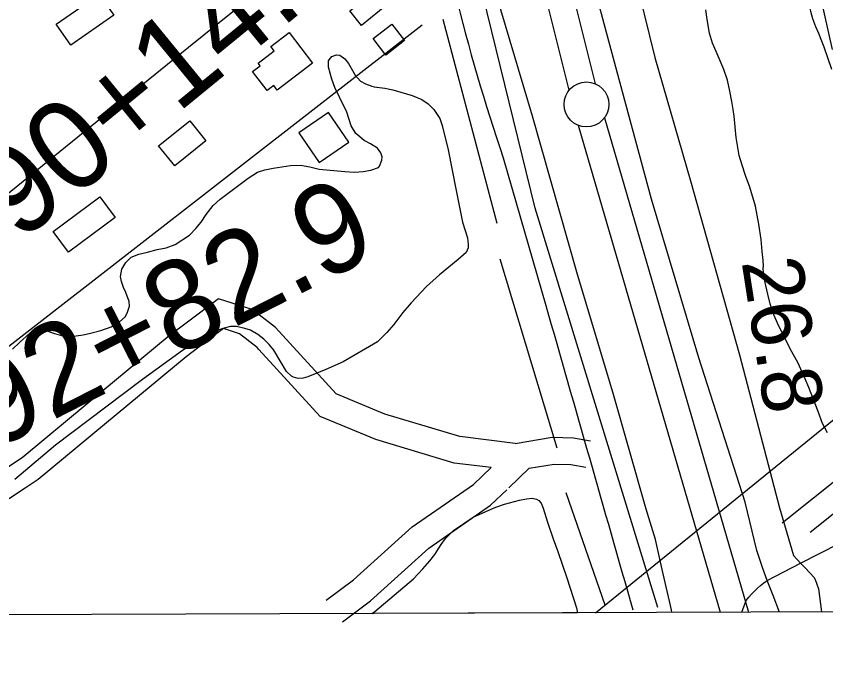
# Model space of a CAD drawing. Extents: x 3392644 to 3430565, y 576657 to 602123.
# Drawn here: x 3411444 to 3412346, y 582044 to 582765 of the extents above; entities that cross this region are included whole.
import ezdxf

# ---------------------------------------------------------------- set-up
doc = ezdxf.new("R2010")
doc.units = 0
for name, color, linetype in [('V-BLDG-OTLN', 7, 'Continuous'), ('V-FLOD-BASE', 7, 'Continuous'), ('V-GRID-FRAM', 7, 'Continuous'), ('V-LEVE-TOET', 7, 'Continuous'), ('V-RIVR-EDGE', 7, 'Continuous'), ('V-RIVR-RANG', 7, 'Continuous'), ('V-ROAD-CNTR', 7, 'Continuous'), ('V-SITE-VEGE', 7, 'Continuous'), ('V-SURV-IDEN', 7, 'Continuous'), ('V-SURV-LINE', 7, 'Continuous'), ('V-TOPO-MAJR', 7, 'Continuous'), ('V-TOPO-SHOR', 7, 'Continuous'), ('V-UTIL-LINE', 7, 'Continuous')]:
    doc.layers.add(name, color=color, linetype=linetype)

msp = doc.modelspace()

# ---------------------------------------------------------------- linework, layer by layer
at = {"layer": 'V-BLDG-OTLN'}
for points in [[(3411832.63, 582811.53), (3411859.31, 582778.84), (3411829.24, 582754.3), (3411816.1, 582770.4), (3411824.16, 582776.98), (3411810.45, 582793.78), (3411814.35, 582796.97), (3411795.96, 582819.5), (3411810.22, 582831.14), (3411828.78, 582808.39)], [(3411488.82, 582755.72), (3411536.7, 582788.93), (3411552.95, 582765.51), (3411505.06, 582732.31)], [(3411842.08, 582739.53), (3411862.93, 582755.51), (3411876.9, 582737.29), (3411856.04, 582721.3)], [(3411748.52, 582746.25), (3411774.49, 582712.2), (3411735.17, 582682.21), (3411731.29, 582687.29), (3411723.9, 582681.65), (3411707.78, 582702.77), (3411716.22, 582709.21), (3411713.94, 582712.2), (3411731.75, 582725.79), (3411728.06, 582730.64)], [(3411814.87, 582624.05), (3411792.4, 582657.14), (3411759.31, 582634.66), (3411781.78, 582601.57)], [(3411602.97, 582620), (3411637.74, 582648), (3411655.72, 582625.68), (3411620.93, 582597.69)], [(3411485.41, 582524.63), (3411537.5, 582563.22), (3411554.58, 582540.16), (3411502.49, 582501.58)]]:
    msp.add_lwpolyline(points, close=True, dxfattribs=at)
at = {"layer": 'V-FLOD-BASE'}
msp.add_lwpolyline([(3412294.62, 582100.75), (3412287.6, 582119.38), (3412281.06, 582136.05), (3412275.85, 582150.62), (3412269.35, 582169.34), (3412256.7, 582223.32), (3412204.93, 582384.16), (3412152.12, 582560.85), (3412109.91, 582717.36), (3412076.65, 582840.63), (3412048.08, 582957.6), (3412030.67, 583048.18), (3412005.56, 583165.77), (3411982.6, 583287.44), (3411961.04, 583410.47), (3411927.14, 583602.61), (3411896.14, 583801.58), (3411869.45, 583976.36), (3411833.6, 584207.11), (3411801.9, 584439.15), (3411784.08, 584609.62), (3411753.14, 584878.14), (3411722.93, 585082.61), (3411689.16, 585314)], dxfattribs=at)
at = {"layer": 'V-GRID-FRAM'}
msp.add_lwpolyline([(3396720.28, 600227.69), (3428325.66, 600342.61), (3428399.71, 582159.31), (3396778.46, 582044.33), (3396720.28, 600227.69)], dxfattribs=at)
at = {"layer": 'V-LEVE-TOET'}
for points in [[(3412175, 582100.31), (3412174.32, 582103.31), (3412164.23, 582148.28), (3412156.65, 582181.5), (3412146.34, 582215.45), (3412109.09, 582345.69), (3412069.79, 582476.66), (3412019.73, 582653.3), (3411984.31, 582771.79), (3411971.61, 582823.7), (3411961.49, 582867.29), (3411950.16, 582918.49), (3411938.26, 582975.89), (3411926.49, 583039.49), (3411908, 583144.55), (3411879.35, 583290.45), (3411840.3, 583499.91), (3411822.94, 583626.29), (3411814.63, 583690.51), (3411806.24, 583751.28), (3411782.23, 583888.82), (3411743.44, 584110.68), (3411705.8, 584355.24)], [(3411869.27, 584216.03), (3411899.49, 584046), (3411940.43, 583794.49), (3411962.95, 583651.47), (3411998.43, 583468.93), (3412031.9, 583256.14), (3412043.28, 583207.01), (3412070.87, 583076.29), (3412107.48, 582915.07), (3412155.75, 582718.5), (3412195.61, 582581.32), (3412250.13, 582387.37), (3412294.81, 582217.04), (3412310.23, 582163.7), (3412318.26, 582155.33), (3412323.04, 582150.35), (3412329.11, 582144.03), (3412333.15, 582139.81), (3412334.47, 582137.03), (3412338.39, 582126.62), (3412341.44, 582100.92)]]:
    msp.add_lwpolyline(points, dxfattribs=at)
at = {"layer": 'V-RIVR-EDGE'}
msp.add_spline([(3412059.19, 585196.29), (3412062.07, 585176.55), (3412061.68, 585167.77), (3412066.02, 585148.02), (3412070.01, 585133.76), (3412072.16, 585119.13), (3412074.7, 585110.35), (3412079.78, 585095.72), (3412081.23, 585089.5), (3412079.74, 585078.54), (3412079.36, 585072.32), (3412081.17, 585067.57), (3412084.46, 585067.19), (3412095.07, 585068.63), (3412098.72, 585067.52), (3412101.26, 585058.38), (3412103.39, 585032.42), (3412101.55, 585030.23), (3412098.62, 585028.41), (3412097.52, 585027.31), (3412097.52, 585024.39), (3412102.98, 585018.16), (3412107.71, 585007.18), (3412106.91, 584977.94), (3412102.84, 584958.58), (3412103.52, 584940.3), (3412103.51, 584934.09), (3412107.14, 584926.4), (3412112.99, 584923.83), (3412115.53, 584916.51), (3412114.78, 584908.47), (3412113.67, 584905.55), (3412117.32, 584901.15), (3412119.86, 584893.83), (3412124.19, 584870.79), (3412130.67, 584830.93), (3412135.72, 584804.6), (3412137.88, 584792.53), (3412134.94, 584783.4), (3412138.14, 584748.3), (3412137.02, 584737.7), (3412137.35, 584723.45), (3412141.69, 584704.79), (3412149.65, 584674.07), (3412155.42, 584639.32), (3412160.84, 584615.18), (3412165.17, 584590.32), (3412166.24, 584579.71), (3412169.13, 584565.08), (3412169.11, 584558.5), (3412167.64, 584554.85), (3412164.34, 584551.94), (3412166.85, 584533.29), (3412168.28, 584519.03), (3412171.16, 584502.2), (3412177.29, 584467.83), (3412184.18, 584443.68), (3412191.41, 584410.04), (3412199.71, 584367.61), (3412203.63, 584329.22), (3412206.83, 584289), (3412206.41, 584269.26), (3412208.92, 584247.69), (3412213.59, 584216.97), (3412216.5, 584210.38), (3412220.87, 584204.53), (3412226.72, 584202.32), (3412230.37, 584203.77), (3412233.29, 584201.57), (3412234.37, 584193.53), (3412234, 584192.06), (3412230.34, 584190.61), (3412233.23, 584174.15), (3412237.92, 584149.65), (3412243.71, 584125.51), (3412250.95, 584099.54), (3412250.94, 584093.69), (3412249.09, 584083.46), (3412250.16, 584076.15), (3412275.2, 584001.51), (3412285.34, 583961.28), (3412288.92, 583930.56), (3412290.33, 583910.09), (3412289.21, 583900.22), (3412292.08, 583879.38), (3412299.34, 583856.33), (3412308.04, 583829.26), (3412312.72, 583799.27), (3412319.18, 583750.64), (3412320.96, 583731.26), (3412329.26, 583686.64), (3412338.66, 583647.14), (3412344.41, 583604.35), (3412350.16, 583567.42), (3412358.82, 583520.61), (3412365.28, 583471.61), (3412371.75, 583429.19), (3412374.99, 583407.98), (3412379.36, 583398.83), (3412379.34, 583391.15), (3412378.96, 583387.86), (3412376.75, 583379.83), (3412374.91, 583375.45), (3412373.43, 583366.68), (3412373.76, 583353.88), (3412378.83, 583331.94), (3412382.46, 583325.35), (3412385.73, 583315.1), (3412394.11, 583305.21), (3412394.46, 583299.73), (3412394.44, 583288.03), (3412393.68, 583278.53), (3412393.65, 583267.93), (3412397.62, 583244.89), (3412403.03, 583217.82), (3412407.68, 583175.04), (3412422.12, 583100.44), (3412429.01, 583076.66), (3412431.89, 583060.57), (3412431.87, 583051.43), (3412434.39, 583034.97), (3412441.63, 583007.54), (3412451.39, 582962.92), (3412455.36, 582943.9), (3412459.01, 582941.33), (3412460.45, 582932.19), (3412468.39, 582890.5), (3412469.11, 582885.38), (3412468.38, 582884.65), (3412463.99, 582883.93), (3412461.79, 582881.01), (3412462.14, 582876.62), (3412467.57, 582853.21), (3412470.46, 582841.14), (3412473.74, 582838.21), (3412477.03, 582835.28), (3412479.92, 582822.48), (3412500.51, 582724.46), (3412513.18, 582673.98), (3412526.2, 582618.02), (3412557.05, 582528.02), (3412580.26, 582453.02), (3412593.31, 582406.57), (3412604.92, 582372.54), (3412613.62, 582344.01), (3412619.42, 582324.25), (3412629.98, 582308.14), (3412635.42, 582288.76), (3412638.32, 582277.42), (3412649.24, 582259.84), (3412659.04, 582231.67), (3412668.49, 582210.08), (3412681.6, 582191.41), (3412693.62, 582172), (3412707.76, 582126.27), (3412708.45, 582107.63), (3412708.05, 582102.25)], degree=3, dxfattribs=at)
at = {"layer": 'V-ROAD-CNTR'}
for points in [[(3411902.46, 582930.52), (3411896.46, 582928.28), (3411890.54, 582925.84), (3411884.71, 582923.2), (3411878.97, 582920.37), (3411873.33, 582917.34), (3411867.8, 582914.13), (3411862.37, 582910.72), (3411857.07, 582907.14), (3411851.89, 582903.38), (3411846.85, 582899.45), (3411841.94, 582895.34), (3411773.23, 582840.31), (3411704.66, 582785.1), (3411636.22, 582729.73), (3411567.92, 582674.19), (3411357.52, 582503.96), (3411036.69, 582245.97), (3410847.91, 582095.48)], [(3411987.05, 582606.77), (3412034.45, 582442.29)], [(3411726.4, 582422.94), (3411707.18, 582437.86), (3411669.78, 582449.85), (3411635.12, 582423.74)], [(3411635.12, 582423.74), (3411614.93, 582408.54), (3411523.56, 582332.87), (3411450.84, 582272.52), (3411430.26, 582258.96)], [(3412000.41, 582288.76), (3411938.65, 582296.25), (3411855.11, 582321.32), (3411800.81, 582343.97), (3411777.05, 582369.82), (3411733.22, 582417.64), (3411726.4, 582422.94)], [(3411714.74, 582393.41), (3411712.82, 582395.5), (3411692.97, 582410.91), (3411675.41, 582416.54), (3411663.57, 582407.62)], [(3411663.57, 582407.62), (3411633.53, 582384.99), (3411542.7, 582309.78), (3411468.72, 582248.38), (3411454.46, 582238.98)], [(3411973.43, 582261.81), (3411932.49, 582266.78), (3411844.99, 582293.03), (3411783.19, 582318.82), (3411754.95, 582349.53), (3411714.74, 582393.41)], [(3412000.41, 582288.76), (3412041.61, 582295.66), (3412065.36, 582295.08), (3412084.39, 582291.65)], [(3411993.35, 582239.36), (3412015.97, 582260.95), (3412043.74, 582265.6), (3412062.32, 582265.15), (3412079.06, 582262.12)], [(3411454.46, 582238.98), (3411419.06, 582215.65), (3411397.09, 582214.5), (3411366.88, 582237.13), (3411340.59, 582262.39)], [(3411789.88, 582114.1), (3411820.17, 582136.73), (3411885.33, 582195.59), (3411953.82, 582243.1), (3411973.43, 582261.81)], [(3411807.84, 582090.07), (3411839.24, 582113.53), (3411904.01, 582172.04), (3411972.84, 582219.78), (3411991.02, 582237.13)], [(3412252.9, 582100.59), (3412257.79, 582113.7), (3412260.66, 582117.36), (3412263.7, 582120.88), (3412266.89, 582124.24), (3412270.23, 582127.45), (3412273.71, 582130.5), (3412277.33, 582133.36), (3412281.06, 582136.05), (3412318.26, 582155.33), (3412425.48, 582210.06)]]:
    msp.add_lwpolyline(points, dxfattribs=at)
for centre, radius, start, end in [((3414058.65, 583313.78), 2188.92, 188.7684, 198.84414), ((3816636.06, 697993.69), 420778.55, 195.9389807, 195.9869919)]:
    msp.add_arc(centre, radius, start, end, dxfattribs=at)
at = {"layer": 'V-SITE-VEGE'}
for p, q in [((3412013.03, 582226.78), (3412019.33, 582227.54)), ((3412019.33, 582227.54), (3412024.13, 582226.75)), ((3411978.84, 582217.76), (3411988.24, 582221.1)), ((3411988.24, 582221.1), (3412005.14, 582225.47)), ((3412005.14, 582225.47), (3412013.03, 582226.78)), ((3412024.13, 582226.75), (3412026.65, 582225.03)), ((3412026.65, 582225.03), (3412029.24, 582222.03)), ((3412029.24, 582222.03), (3412031.58, 582216.47)), ((3411953.45, 582206.69), (3411967.53, 582212.69)), ((3411967.53, 582212.69), (3411978.84, 582217.76)), ((3412031.58, 582216.47), (3412036.17, 582200.95)), ((3411931.72, 582191.71), (3411953.45, 582206.69)), ((3412036.17, 582200.95), (3412042.67, 582182.54)), ((3411922.69, 582182.76), (3411931.72, 582191.71)), ((3411917.74, 582176.09), (3411922.69, 582182.76)), ((3412042.67, 582182.54), (3412047.88, 582168.18)), ((3411910.63, 582165.03), (3411917.74, 582176.09)), ((3411905.08, 582157.97), (3411910.63, 582165.03)), ((3412047.88, 582168.18), (3412057.79, 582138.99)), ((3411897.43, 582148.89), (3411905.08, 582157.97)), ((3411887.18, 582137.9), (3411897.43, 582148.89)), ((3411843.97, 582101.65), (3411887.18, 582137.9)), ((3412057.79, 582138.99), (3412068.49, 582105.46)), ((3411840.39, 582099.09), (3411843.97, 582101.65)), ((3412068.49, 582105.46), (3412069.68, 582099.93)), ((3412069.68, 582099.93), (3411840.39, 582099.09))]:
    msp.add_line(p, q, dxfattribs=at)
for points in [[(3412325.99, 582783.24), (3412327.64, 582777.42), (3412329.45, 582770.12), (3412331.44, 582761.83), (3412334.79, 582753.02), (3412338.37, 582745.49), (3412344.24, 582730.45), (3412352.65, 582705.44)], [(3412348.1, 582300.42), (3412342.83, 582311.04), (3412337.8, 582324.19), (3412331.93, 582339.63), (3412327.35, 582350.82), (3412323.34, 582360.72), (3412315.55, 582377.96), (3412306.85, 582394.14), (3412301.66, 582403.96), (3412294.21, 582419.14), (3412287.46, 582434.39), (3412284.53, 582444.27), (3412281.7, 582454.83), (3412279.45, 582464.5), (3412277.75, 582472.68), (3412276.83, 582480.16), (3412276.58, 582482.42), (3412276.51, 582483.9), (3412276.85, 582485.75), (3412276.6, 582492.63), (3412275.62, 582502.46), (3412274.22, 582515.65), (3412271.93, 582532.97), (3412267.93, 582552.88), (3412261.79, 582574.11), (3412257.05, 582587.07), (3412253.07, 582598.74), (3412249.95, 582609.21), (3412248.02, 582620.34), (3412246.35, 582629.4), (3412244.19, 582653.2), (3412243.16, 582660.59), (3412241.68, 582669.45), (3412239.46, 582680.98), (3412236.87, 582693.21), (3412232.8, 582705.27), (3412227.55, 582717.45), (3412224.08, 582725.18), (3412220.15, 582734.58), (3412216.75, 582745.65), (3412214.02, 582760.73), (3412212.67, 582771.45)], [(3411440.31, 582393.81), (3411448.12, 582401.11), (3411463.14, 582414.85), (3411467, 582416.35), (3411470.85, 582416.86), (3411474.66, 582415.8), (3411479.53, 582413.83), (3411487.04, 582411.02), (3411497.5, 582408.25), (3411506.13, 582407.78), (3411519.04, 582409.47), (3411527.13, 582411.37), (3411538.6, 582414.57), (3411550.17, 582418.36), (3411558.93, 582423.59), (3411565.94, 582429.92), (3411568.3, 582434.69), (3411570.7, 582441.52), (3411570.32, 582446.93), (3411566.4, 582456.84), (3411563.86, 582462.39), (3411561.73, 582468.92), (3411560.67, 582474.74), (3411562.12, 582482.77), (3411566.5, 582490.34), (3411572.52, 582496.31), (3411580.84, 582499.38), (3411590.61, 582501.73), (3411601.48, 582504.55), (3411611.25, 582506.71), (3411621.35, 582510.23), (3411637.28, 582520.52), (3411644.42, 582528.13), (3411650.26, 582535.08), (3411655.84, 582543.81), (3411663.91, 582553.67), (3411671.62, 582560.88), (3411687.99, 582573.02), (3411702.76, 582584.21), (3411713.12, 582590.87), (3411721.52, 582593.35), (3411730.8, 582595.42), (3411749.83, 582598.37), (3411761.13, 582598.43), (3411771.51, 582596.74), (3411781.97, 582594.16), (3411798.34, 582592.55), (3411810.6, 582591.51), (3411821.3, 582590.89), (3411830.84, 582591.39), (3411839.62, 582592.97), (3411848.04, 582596.04), (3411849.15, 582597.49), (3411851.64, 582604.02), (3411851.92, 582607.95), (3411850.63, 582612.49), (3411846.81, 582617.39), (3411839.05, 582622.36), (3411831.95, 582626.05), (3411822.68, 582634), (3411817.65, 582642.46), (3411812.76, 582657.69), (3411804.65, 582674.36), (3411799.28, 582685.19), (3411795.93, 582694.3), (3411792.38, 582707.93), (3411792.42, 582714.81), (3411792.94, 582716.07), (3411796.16, 582719.74), (3411801.21, 582721.6)], [(3411801.21, 582721.6), (3411804.83, 582721.03), (3411810.45, 582717.08), (3411814.76, 582711.89), (3411821.87, 582698.97), (3411827.92, 582692.35), (3411833.55, 582689.29), (3411840.67, 582686.59), (3411843.31, 582685.95), (3411855.07, 582684.33), (3411863.87, 582682.38), (3411872.77, 582680.03), (3411885.46, 582676.23), (3411896.27, 582671.59), (3411903.35, 582666.92), (3411909.81, 582660.79), (3411916.37, 582650.44), (3411919.06, 582642.62), (3411925.58, 582615.76), (3411934.56, 582570.37), (3411941.59, 582535.15), (3411947.13, 582517.64), (3411948.06, 582510.25), (3411948.08, 582506.62), (3411945.61, 582501.26), (3411936.7, 582493.49), (3411916.01, 582476.43), (3411901.3, 582463.47), (3411884.51, 582445.24), (3411875.15, 582434.43), (3411865.14, 582420.98), (3411857.3, 582412.2), (3411846.77, 582401.71), (3411808.48, 582379.51), (3411789.34, 582371.16), (3411769.12, 582362.74), (3411764.08, 582361.37), (3411758.47, 582361.09), (3411753.2, 582362.58), (3411750.96, 582363.7), (3411745.47, 582368.93), (3411731.42, 582392.6), (3411726.24, 582398.8), (3411720.27, 582404.82), (3411713.5, 582409.97), (3411705.35, 582414.66), (3411699.2, 582416.65), (3411689.71, 582418.92), (3411683.13, 582418.85), (3411674.63, 582416.77), (3411660.87, 582411.45), (3411640.17, 582398.71), (3411629.72, 582392.35)], [(3411629.72, 582392.35), (3411584.93, 582359.87), (3411544.2, 582329.17), (3411488.3, 582286.8), (3411442.8, 582248.34)]]:
    msp.add_lwpolyline(points, dxfattribs=at)
at = {"layer": 'V-SURV-LINE'}
for points in [[(3412034.1, 582910.95), (3412089.42, 582689.28)], [(3412060.31, 582682.03), (3412004.99, 582903.7)], [(3412099.7, 582651.31), (3412260.39, 582100.62)], [(3412229.17, 582100.51), (3412070.9, 582642.89)]]:
    msp.add_lwpolyline(points, dxfattribs=at)
msp.add_circle((3412079.7, 582666.28), 25, dxfattribs=at)
at = {"layer": 'V-TOPO-MAJR'}
msp.add_lwpolyline([(3412068.77, 584210), (3412080.72, 584121.96), (3412099.32, 583984.93), (3412102.12, 583965.43), (3412105.12, 583945.95), (3412108.43, 583926.53), (3412111.93, 583907.14), (3412150.96, 583700.39), (3412167.74, 583612.11), (3412184.67, 583523.87), (3412201.83, 583435.67), (3412219.14, 583347.49), (3412241.6, 583233.84), (3412247.91, 583202.54), (3412254.38, 583171.28), (3412261.09, 583140.06), (3412267.96, 583108.88), (3412353.57, 582727.46)], dxfattribs=at)
at = {"layer": 'V-TOPO-SHOR'}
for p, q in [((3411919.58, 582761.29), (3411979.77, 582533.97)), ((3411983.21, 582494.41), (3412046.63, 582283.59)), ((3412056.7, 582234.16), (3412100.03, 582109))]:
    msp.add_line(p, q, dxfattribs=at)
for points in [[(3412159.4, 582105.92), (3412022.58, 582550.61), (3411925.51, 582945.98), (3411851.76, 583275.49), (3411770.46, 583868.78), (3411738.54, 584036.56)], [(3411896.52, 582754.61), (3411350.65, 582330.52), (3411140.23, 582154.98), (3411081.05, 582105.3)]]:
    msp.add_lwpolyline(points, dxfattribs=at)
at = {"layer": 'V-UTIL-LINE'}
for p, q in [((3412297.94, 582200.06), (3415100.62, 584449.07)), ((3412328.89, 582189.74), (3415131.57, 584438.76))]:
    msp.add_line(p, q, dxfattribs=at)
msp.add_lwpolyline([(3412089.87, 582100), (3412530.99, 582457.84), (3414603.59, 584199.19), (3415068.56, 584289.48), (3415163.54, 584253.48), (3416142.94, 584475.33), (3415963.69, 585213.99)], dxfattribs=at)

# ---------------------------------------------------------------- texts
at = {"layer": 'V-RIVR-RANG'}
msp.add_text('26.8', height=67, rotation=278.77833, dxfattribs=at).set_placement((3412252.48, 582491.23))
at = {"layer": 'V-SURV-IDEN'}
for s, rotation, p in [('390+14.4', 39.32236, (3411390.6, 582464.53)), ('392+82.9', 27.03654, (3411351.05, 582245.86))]:
    msp.add_text(s, height=100, rotation=rotation, dxfattribs=at).set_placement(p)

doc.saveas('drawing.dxf')
